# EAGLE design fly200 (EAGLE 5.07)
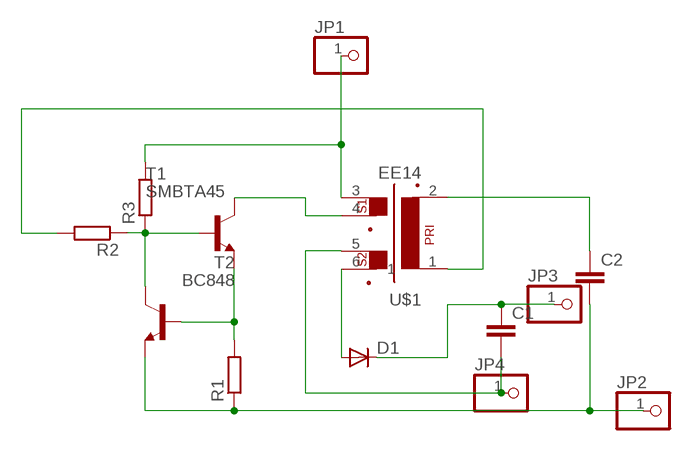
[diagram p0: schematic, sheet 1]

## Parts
C1  C-EU025-025X050  [C025-025X050]
C2  C-EUC0805  [C0805]
D1  DIODE-SMA-DO214  [SMA-DO214AC]
JP1  PINHD-1X11MM6  [1X1MM8]
JP2  PINHD-1X11MM6  [1X1MM8]
JP3  PINHD-1X11MM6  [1X1MM8]
JP4  PINHD-1X11MM6  [1X1MM8]
R1  R-EU_R0805  [R0805]
R2  R-EU_R0805  [R0805]
R3  R-EU_0204/2V  [0204V]
T1  SMBTA45  BC848  [SOT23]
T2  BC848  [SOT23]
U$1  EE14  [EE14]

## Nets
A: D1.A U$1.6
B1C2: R2.1 R3.1 T1.B T2.C
C1: T1.C U$1.4
EB: R1.2 T1.E T2.B
N$4: R2.2 U$1.1
N$6: C2.1 U$1.2
V+: JP1.1 R3.2 U$1.3
V-: C2.2 JP2.1 R1.1 T2.E
VOUT: C1.2 JP4.1 U$1.5
VOUT-: C1.1 D1.K(C) JP3.1

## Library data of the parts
C1 C2 = rcl:C-EU: CAPACITOR, European symbol
D1 = diode:DIODE-: DIODE
JP1-JP4 = pinhead:PINHD-1X1: PIN HEADER
R1-R3 = rcl:R-EU_: RESISTOR, European symbol
T1 T2 = transistor:BC848: NPN TRANSISTOR
U$1 = trafo:EE14

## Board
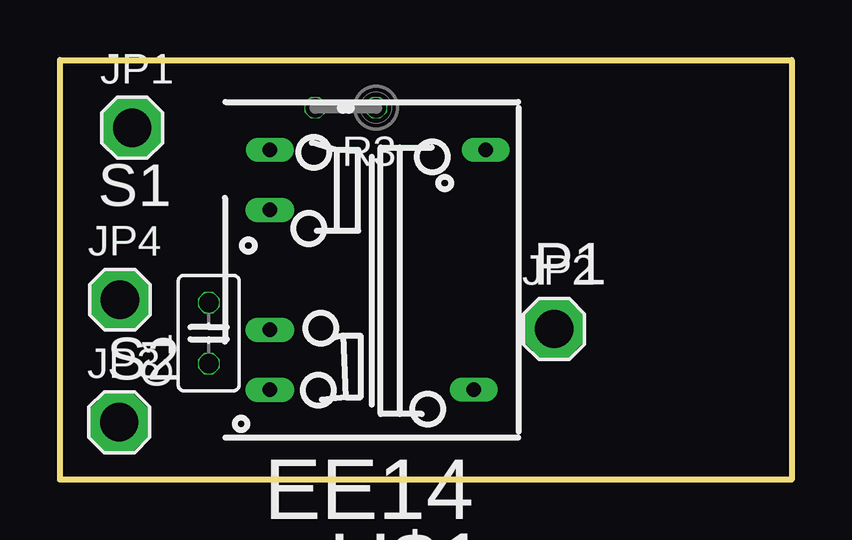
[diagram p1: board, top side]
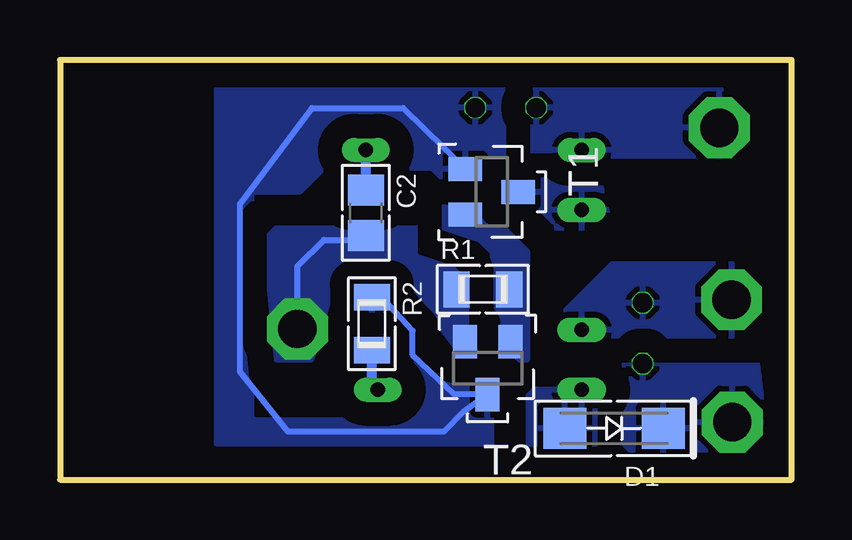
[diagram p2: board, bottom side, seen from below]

Size 30.5 x 17.5 mm. Coordinates in mm from the lower left corner, seen from the top.
Outline: 0,17.5 30.5,17.5 30.5,0 0,0 0,17.5
Copper layers (1*16): Top 0.035mm / dielectric 1.5mm / Bottom 0.035mm
Design rules "default": minimum track width 10mil, minimum drill 20mil, track to track 8mil, track to pad 8mil, pad to pad 8mil, via to via 8mil, smd to smd 8mil, copper to edge 40mil, drill to drill 8mil, minimum pad ring 1mil, minimum via ring 8mil, stop-mask expansion 4mil, vias tented up to drill 0mil, thermal gap 10mil

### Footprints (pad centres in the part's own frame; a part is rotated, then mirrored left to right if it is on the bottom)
C025-025X050 = drill 0.813 octagon: 1 -1.27,0; 2 1.27,0
C0805 = smd 1.3 x 1.5: 1 -0.95,0; 2 0.95,0
SMA-DO214AC = smd 1.8 x 1.7: A 2.05,-0.127; K -2.05,-0.127
1X1MM8 = drill 1.6 pad 2.54 octagon: 1 0,0
R0805 = smd 1.1 x 1.5: 1 -1.1,0; 2 1.1,0
0204V = drill 0.813 octagon: 1 -1.27,0; 2 1.27,0
SOT23 = smd 1 x 1.4: B -0.95,-1.1; C 0,1.1; E 0.95,-1.1
EE14 = drill 0.6 pad 1 long: 1 4.25,-5; 2 4.75,5; 3 -4.25,5 | drill 0.6 pad 1.016 long: 4 -4.25,2.5; 5 -4.25,-2.5; 6 -4.25,-5

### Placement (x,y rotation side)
C1  6.2,6.11 90 top
C2  17.75,11.12 270 bottom
D1  7.39,2.01 180 bottom
JP1  3.01,14.67 0 top
JP2  20.6,6.28 0 top
JP3  2.47,2.39 0 top
JP4  2.5,7.5 0 top
R1  12.87,7.93 0 bottom
R2  17.5,6.5 270 bottom
R3  11.91,15.51 180 top
T1  12.5,12 270 bottom
T2  12.67,4.64 180 bottom
U$1  13,8.75 0 top

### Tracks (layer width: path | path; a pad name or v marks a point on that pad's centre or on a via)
A
  pour Bottom (isolate 1, rank 3): 8,4 10.5,4 11,3.5 11,1.5 8,1.5
B1C2
  Bottom 0.254: T1.B 16.19,15.5 20,15.5 23,11.5 23,4.5 21,2 14.5,2 13.67,2.83 T2.C 14.04,3.54 15.8,5.2 15.8,6.2 17,7.5 17.51,7.5 R2.1
  pour Bottom (isolate 1, rank 3): 12,16.5 24,16.5 24,1.5 12.5,1.5 12.5,4.5 14,4.5 15,5.5 15.5,7 18.5,7.5 18.5,2.5 22.5,2.5 22.5,12 20.5,12 19.5,13 15,13 14,12 13.5,12 12,13.5
C1
  pour Bottom (isolate 1, rank 3): 8,12.5 11,12.5 11,10.5 7.5,10.5
EB
  pour Bottom (isolate 1, no thermals): 11,5 11,9.5 13,11.5 14.5,11.5 14.5,10.5 13,10 12.5,9.5 12.5,5.5 12,5
N$4
  Bottom 0.406: U$1.1 17.5,3.75 R2.2
N$6
  Bottom 0.406: C2.1 U$1.2
V+
  pour Bottom (isolate 1, rank 4): 3,16.5 10.5,16.5 11,16 11,13.5 2,13.5
V-
  Bottom 0.254: JP2.1 20.6,8.9 19.5,10 17.93,10 C2.2
  pour Bottom (isolate 1, rank 2, no thermals): 15.5,10.5 21.5,10.5 22,10 21.5,5 20,5 19,8.5 16,8.5 16,7.5 15.5,7.5 15.1,6.9 14,5.5 13.2,5.4 13.3,8.3
VOUT
  pour Bottom (isolate 1): 1.5,9 7.5,9 9.5,7 9.5,6 2,6 1.5,6.5
VOUT-
  pour Bottom (isolate 1, rank 2): 1.5,5.5 7,5.5 7,1.5 6.5,1 1.5,1 1,1.5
